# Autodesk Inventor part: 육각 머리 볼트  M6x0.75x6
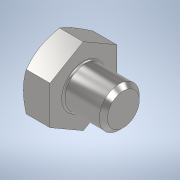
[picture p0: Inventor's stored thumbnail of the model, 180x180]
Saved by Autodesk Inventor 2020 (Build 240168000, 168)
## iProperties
Created: 2024-05
Part Number: 육각 머리 볼트  M6x0.75x6
Material: 강철, 연강
Description: 6각 머리 볼트 및 6각 머리 나사
Document SubType Name: Modeling
Designer: oem
Density: 7.85 g/cm^3
Appearance: 기본값
Author: jhkim
Sending System: Autodesk Inventor 2025
Preprocessor: ST-DEVELOPER v20
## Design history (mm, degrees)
node "육각 머리 볼트  M6x0.75x61"
node "솔리드1"
body "Solid1"
